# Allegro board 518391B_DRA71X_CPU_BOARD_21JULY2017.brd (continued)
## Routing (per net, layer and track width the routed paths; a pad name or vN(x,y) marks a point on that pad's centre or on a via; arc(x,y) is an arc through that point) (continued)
H_CSI2_DX1: length 83.1
  TOP w0.112: U27.AD1 100.85,91.95 101.61,91.95 102.39,92.73 102.39,93.49 103.14,94.23 108.58,94.23 108.74,94.08 109.45,94.08 115.7,100.33 133.99,100.33 136.8,97.51 151.24,97.51 151.74,98.02 156.36,98.02 157.2,97.18 157.2,95.4 157.48,95.12 157.48,93.63 157.67,93.45 158.86,93.45 159.06,93.65 159.06,95.95 159.38,96.27 159.89,96.27 160.21,95.95 160.21,94.7 160.43,94.49 163.01,94.49 163.37,94.13 163.37,91.97 163.79,91.55 164.05,91.55 164.16,91.66 164.16,91.96 164.27,92.07 164.49,92.07 164.6,91.96 164.6,91.66 164.72,91.55 164.95,91.55 165.16,91.76 v2(165.54,91.76)
  BOTTOM w0.112: v2(165.54,91.76) 165.41,91.62 P9.9
H_CSI2_DX2: length 82.3
  TOP w0.102: U27.AE2 100.11,92.62 100.12,92.62 100.12,92.8
  TOP w0.112: 100.12,92.8 100.12,93 102.24,95.12 108.46,95.12 114.81,101.47 134.49,101.47 137.03,98.93 151.14,98.93 151.24,99.03 160.68,99.03 163.82,95.89 163.82,95.64 164.08,95.38 v2(164.35,95.38)
  BOTTOM w0.112: v2(164.35,95.38) 164.08,95.38 163.82,95.64 163.82,96 163.96,96.14 164.6,96.14 166.07,94.66 166.07,93.05 165.85,92.82 165.72,92.82 165.61,92.71 165.61,92.51 165.75,92.38 165.94,92.38 166.07,92.25 166.07,90.12 165.93,89.98 165.29,89.98 165.14,90.13 P9.13
H_CSI2_DY0: length 82.6
  TOP w0.102: 101.15,90.88 100.44,90.88 U27.AB2
  TOP w0.112: 101.15,90.88 102.18,90.88 103.25,91.95 109.98,91.95 116.74,98.7 133.08,98.7 135.64,96.14 138.2,96.14 138.31,96.03 138.31,95.44 138.63,95.12 139.15,95.12 139.47,95.44 139.47,96.03 139.58,96.14 139.82,96.14 139.93,96.03 139.93,95.57 140.25,95.25 140.77,95.25 141.09,95.57 141.09,96.03 141.2,96.14 141.44,96.14 141.55,96.03 141.55,95.32 141.87,95 142.39,95 142.71,95.32 142.71,96.03 142.82,96.14 143.05,96.14 143.16,96.03 143.16,95.32 143.48,95 144,95 144.32,95.32 144.32,96.03 144.43,96.14 144.65,96.14 144.76,96.03 144.76,95.32 145.08,95 145.6,95 145.92,95.32 145.92,96.03 146.03,96.14 146.26,96.14 146.37,96.03 146.37,95.32 146.69,95 147.21,95 147.53,95.32 147.53,96.03 147.64,96.14 147.86,96.14 147.98,96.03 147.98,95.32 148.3,95 148.81,95 149.13,95.32 149.13,96.03 149.25,96.14 149.48,96.14 154.44,91.19 156.21,91.19 156.49,91.47 158.9,91.47 160.02,92.58 v2(162.31,92.58)
  BOTTOM w0.112: v2(162.31,92.58) 162.35,92.62 P9.7
H_CSI2_DY1: length 83.1
  TOP w0.102: 100.97,91.57 100.92,91.51 100.58,91.51 100.28,91.21 U27.AC2
  TOP w0.112: 100.97,91.57 100.98,91.57 101,91.59 101.76,91.59 102.75,92.58 102.75,92.8 102.75,93.34 103.29,93.88 108.43,93.88 108.59,93.72 109.6,93.72 115.85,99.97 133.84,99.97 136.66,97.16 151.38,97.16 151.89,97.66 156.21,97.66 156.84,97.03 156.84,95.26 157.12,94.98 157.12,93.49 157.52,93.09 159,93.09 159.41,93.5 159.41,95.8 159.52,95.91 159.75,95.91 159.86,95.8 159.86,94.55 160.28,94.13 162.86,94.13 163.02,93.98 163.02,91.82 163.64,91.2 164.96,91.2 165.16,91 v2(165.55,91)
  BOTTOM w0.112: v2(165.55,91) 165.42,91.13 P9.11
H_CSI2_DY2: length 82.3
  TOP w0.102: U27.AD2 100.12,92.02 100.44,92.34 100.44,92.76 100.47,92.8
  TOP w0.112: v2(163.46,95.38) 163.46,95.74 160.53,98.68 151.38,98.68 151.28,98.58 136.89,98.58 134.35,101.12 114.96,101.12 108.61,94.77 102.39,94.77 100.47,92.85 100.47,92.8
  BOTTOM w0.112: v2(163.46,95.38) 163.46,96.15 163.81,96.49 164.74,96.49 166.43,94.81 166.43,89.97 166.08,89.63 P9.15
H_DCAN1_RX: length 112
  TOP w0.127: v2(68.8,64.39) 68.8,64.43 68.71,64.52 68.71,69.05 68.25,69.5 v2(68.25,70.23) ; v1(86.14,81.13) U27.H23
  LY3 w0.133: v2(68.8,64.39) 70.36,62.83 70.36,53.21 75.06,48.51 75.06,47.37 76.58,45.85 76.58,42.54 80.77,38.35 106.68,38.35 110.87,34.16 123.82,34.16 124.84,35.18 127.25,35.18 129.03,36.96 v2(129.07,36.96)
  LY4 w0.133: v1(86.14,81.13) 84.13,79.12 83.95,79.12 82.17,77.34 81.28,77.34 80.39,76.45 79.38,76.45 77.22,74.3 76.34,74.3 74.94,72.9 71.62,72.9 69.34,70.62 69.34,70.61 68.96,70.23 v2(68.25,70.23)
  BOTTOM w0.127: R371.1 129.03,36.92 v2(129.07,36.96)
H_DCAN1_TX: length 120.9
  TOP w0.127: v1(86.79,81.13) U27.H22 ; v2(68.8,70.99) 68.8,69.32 69.01,69.1 69.01,64.85 69.22,64.65 69.22,64.15 v2(68.7,63.64)
  LY3 w0.133: v2(68.7,63.64) 69.85,62.48 69.85,53.21 74.68,48.39 74.68,47.24 76.2,45.72 76.2,42.42 86.74,31.88 92.84,31.88 94.23,33.27 107.66,33.27 108.55,32.38 119.51,32.38 120.02,32.89 127.51,32.89 130.05,35.43 130.05,37.08 129.54,37.59 128.14,37.59 v2(127.89,37.34)
  LY4 w0.133: v1(86.79,81.13) 86.39,81.53 85.85,81.53 81.92,77.6 80.16,77.6 77.11,74.56 76.23,74.56 74.83,73.16 71.51,73.16 69.35,70.99 v2(68.8,70.99)
  BOTTOM w0.127: R372.1 v2(127.89,37.34)
H_DDR1_A0: length 99.1
  TOP w0.102: U23.N3 v4(54.55,97) ; U29.N3 v4(54.55,82.77)
  TOP w0.127: R88.2 v2(53.85,72.58) ; U27.AC18 v1(90.04,91.53)
  LY3 w0.133: v2(53.85,72.58) 53.85,73.91 54.15,74.21 54.15,79.8 54.55,80.2 v4(54.55,82.77)
  LY4 w0.133: v1(90.04,91.53) 90.04,94.03 89.69,94.38 89.69,94.57 90.06,94.94 90.06,95.13 89.87,95.32 89.68,95.32 89.31,94.95 89.13,94.95 88.94,95.14 88.94,95.33 89.92,96.3 89.92,96.65 88.52,98.04 86.74,98.04 85.75,99.03 85.75,100.31 84.86,101.2 84.64,101.2 83.9,100.47 83.68,100.47 83.53,100.62 83.53,100.84 84.26,101.58 84.26,101.8 84.07,101.98 83.19,101.98 82.38,101.18 82.38,100.5 82.26,100.39 72.33,100.39 72.24,100.47 71.98,100.47 71.85,100.61 71.85,101.05 71.72,101.18 71.45,101.18 71.32,101.05 71.32,100.61 71.18,100.47 70.92,100.47 70.78,100.61 70.78,101.05 70.65,101.18 70.38,101.18 70.25,101.05 70.25,100.61 70.12,100.47 69.77,100.47 69.63,100.34 69.63,99.59 69.5,99.46 69.23,99.46 69.1,99.59 69.1,100.34 68.97,100.47 68.7,100.47 68.57,100.34 68.57,99.59 68.43,99.46 68.17,99.46 68.03,99.59 68.03,100.34 67.9,100.47 67.63,100.47 67.5,100.34 67.5,99.59 67.37,99.46 67.1,99.46 66.97,99.59 66.97,100.34 66.81,100.5 63.42,100.5 63.26,100.34 63.26,100.11 63.11,99.95 62.89,99.95 62.73,100.11 62.73,100.34 62.57,100.5 62.06,100.5 62,100.56 60.22,100.56 60.06,100.41 60.06,100.11 59.9,99.95 59.68,99.95 59.53,100.11 59.53,100.41 59.37,100.56 59.15,100.56 58.99,100.41 58.99,100.11 58.84,99.95 58.62,99.95 58.46,100.11 58.46,100.41 58.3,100.56 58.04,100.56 57.91,100.43 57.91,99.71 57.78,99.58 57.51,99.58 57.38,99.71 57.38,100.43 57.24,100.56 56.98,100.56 56.84,100.43 56.84,99.71 56.71,99.58 56.44,99.58 56.31,99.71 56.31,100.43 56.18,100.56 55.52,100.56 54.95,99.99 54.95,97.4 v4(54.55,97)
  BOTTOM w0.127: v4(54.55,82.77) 54.14,83.18 54.14,83.73 53.91,83.97 53.55,83.97 53.35,84.16 53.35,84.52 52.71,85.17 52.68,85.17 52.68,88.95 54.95,91.22 54.95,93.38 55.32,93.75 55.32,94.19 55.19,94.31 53.19,94.31 53.06,94.44 53.06,94.7 53.19,94.82 55.19,94.82 55.32,94.95 55.32,95.96 55.04,96.24 54.67,96.24 54.55,96.37 v4(54.55,97)
H_DDR1_A1: length 95.2
  TOP w0.102: U29.P7 v4(53.75,78.77)
  TOP w0.127: v2(85.45,103.9) 85.45,103.2 86.61,102.03 86.61,100.27 88.07,98.81 88.07,98.36 87.55,97.84 87.55,95.9 89.06,94.39 U27.AE19 ; v4(53.75,93) U23.P7
  LY3 w0.133: v2(53.21,73.02) 53.21,73.66 53.09,73.79 53.09,75.43 53.35,75.7 53.35,78.38 v4(53.75,78.77) 53.75,80.1 54.15,80.5 54.15,84.53 53.35,85.33 53.35,85.57 53.22,85.7 52.15,85.7 52.02,85.83 52.02,86.1 52.15,86.23 53.22,86.23 53.35,86.37 53.35,86.63 53.22,86.77 52.15,86.77 52.02,86.9 52.02,87.17 52.15,87.3 53.22,87.3 53.35,87.43 53.35,92.6 v4(53.75,93)
  LY4 w0.133: v2(85.45,103.9) 85.02,103.48 69.24,103.48 68.09,102.33 67.79,102.33 67.66,102.46 67.66,103.41 67.52,103.54 67.26,103.54 67.12,103.41 67.12,102.46 66.99,102.33 66.72,102.33 66.59,102.46 66.59,103.41 66.46,103.54 66.19,103.54 66.06,103.41 66.06,102.46 65.92,102.33 65.66,102.33 65.52,102.46 65.52,103.41 65.39,103.54 65.12,103.54 64.99,103.41 64.99,102.46 64.86,102.33 64.59,102.33 64.46,102.46 64.46,103.41 64.32,103.54 64.06,103.54 63.92,103.41 63.92,102.46 63.79,102.33 63.52,102.33 63.39,102.46 63.39,103.41 63.26,103.54 62.99,103.54 62.86,103.41 62.86,102.46 62.72,102.33 53.98,102.33 51.73,100.08 51.73,96.3 53.75,94.28 v4(53.75,93)
  BOTTOM w0.127: v2(53.21,73.02) R284.2
H_DDR1_A2: length 108.6
  TOP w0.102: 89.39,93.24 89.39,92.18 U27.AD19 ; U23.P3 v4(53.75,97) ; U29.P3 v4(53.75,82.77)
  TOP w0.127: 89.39,93.24 89.39,94.42 87.86,95.95 87.86,97.78 88.33,98.25 88.33,98.92 86.89,100.35 86.89,102.16 86.33,102.72 v2(86.33,103.66) ; R85.2 v2(50.42,72.58)
  LY3 w0.133: v2(50.42,72.58) 50.42,77.7 53.75,81.03 v4(53.75,82.77)
  BOTTOM w0.127: v4(53.75,82.77) 53.35,83.17 52.78,83.17 52.54,83.4 52.54,83.73 52.54,84.67 52.2,85.01 52.2,89.13 54.15,91.09 54.15,92.84 54.14,92.85 54.14,93.64 53.87,93.9 52.98,93.9 52.63,94.26 52.63,95.2 52.76,95.33 54.64,95.33 54.76,95.45 54.76,95.71 54.64,95.83 52.76,95.83 52.63,95.96 52.63,96.22 52.86,96.44 53.59,96.44 53.75,96.6 v4(53.75,97) 53.35,97.39 53.35,104.11 53.77,104.52 54.15,104.52 54.28,104.39 54.28,102.76 54.41,102.64 54.63,102.64 54.79,102.8 54.79,104.39 54.92,104.52 55.17,104.52 55.3,104.39 55.3,102.85 55.46,102.68 55.64,102.68 55.81,102.85 55.81,104.39 55.93,104.52 56.31,104.52 56.44,104.39 56.44,103.6 56.57,103.48 56.82,103.48 56.95,103.6 56.95,104.39 57.07,104.52 57.33,104.52 57.45,104.39 57.45,103.6 57.58,103.48 57.84,103.48 57.96,103.6 57.96,104.39 58.09,104.52 58.34,104.52 58.47,104.39 58.47,103.6 58.6,103.48 58.85,103.48 58.98,103.6 58.98,104.39 59.11,104.52 59.36,104.52 59.49,104.39 59.49,103.6 59.61,103.48 59.87,103.48 59.99,103.6 59.99,104.39 60.12,104.52 60.38,104.52 60.5,104.39 60.5,103.6 60.63,103.48 60.88,103.48 61.01,103.6 61.01,104.39 61.14,104.52 61.39,104.52 61.52,104.39 61.52,103.6 61.65,103.48 61.9,103.48 62.03,103.6 62.03,104.39 62.15,104.52 62.41,104.52 62.53,104.39 62.53,103.6 62.66,103.48 83.24,103.48 84.08,104.32 85.67,104.32 v2(86.33,103.66)
H_DDR1_A3: length 102.3
  TOP w0.102: U23.N2 v4(54.55,97.8) ; U29.N2 v4(54.55,83.57)
  TOP w0.127: v1(87.38,90.8) 88.82,90.8 U27.AB19 ; R90.2 v2(56.13,72.58)
  LY3 w0.133: v2(56.13,72.58) 56.13,75.44 54.95,76.63 54.95,83.17 54.55,83.57 v4(54.55,83.57) 54.95,83.97 54.95,87.8 54.15,88.6 54.15,93.39 54.91,94.16 57.28,94.16 57.58,94.46 57.58,95.28 57.12,95.73 55.83,95.73 54.95,96.61 54.95,97.39 v4(54.55,97.8) 54.95,98.19 54.95,101.4 55.14,101.59 55.14,102.6 55.63,103.09 72.02,103.09 72.78,103.85 77.55,103.85 77.68,103.71 77.68,103.22 77.82,103.09 78.08,103.09 78.22,103.22 78.22,103.71 78.35,103.85 78.62,103.85 78.75,103.71 78.75,103.22 78.88,103.09 79.15,103.09 79.28,103.22 79.28,103.71 79.42,103.85 79.68,103.85 79.82,103.71 79.82,103.22 79.95,103.09 80.22,103.09 80.35,103.22 80.35,103.71 80.48,103.85 80.75,103.85 80.88,103.71 80.88,103.22 81.02,103.09 81.28,103.09 81.42,103.22 81.42,103.71 81.55,103.85 81.82,103.85 81.95,103.71 81.95,103.22 82.08,103.09 82.61,103.09 84.58,101.11 86.81,101.11 87.19,100.74 90.45,100.74 91.44,99.75 91.44,96.49 90.84,95.88 89.5,95.88 88.94,95.33 88.94,92.59 88.81,92.46 88.53,92.46 88.39,92.59 88.39,95.37 88.26,95.5 87.99,95.5 87.86,95.37 87.86,92.35 88.52,91.69 88.52,91.44 87.88,90.8 v1(87.38,90.8)
H_DDR1_A4: length 94.7
  TOP w0.102: U29.P8 v4(53.75,77.97) ; U27.AD20 88.09,92.18 88.09,93.24
  TOP w0.127: 88.09,93.24 88.09,94.28 86.79,95.58 86.79,99.37 85.7,100.47 85.7,102.46 84.89,103.28 84.89,103.57 v2(84.56,103.9) ; v4(53.75,92.2) U23.P8
  LY4 w0.133: v2(84.56,103.9) 62.59,103.9 61.7,103 61.21,103 61.08,103.14 61.08,103.85 60.94,103.98 60.68,103.98 60.54,103.85 60.54,103.14 60.41,103 60.14,103 60.01,103.14 60.01,103.85 59.88,103.98 59.61,103.98 59.48,103.85 59.48,103.14 59.34,103 59.08,103 58.94,103.14 58.94,103.85 58.81,103.98 58.54,103.98 58.41,103.85 58.41,103.14 58.28,103 58.01,103 57.88,103.14 57.88,103.85 57.74,103.98 57.48,103.98 57.34,103.85 57.34,103.14 57.21,103 56.94,103 56.81,103.14 56.81,103.85 56.68,103.98 56.41,103.98 56.27,103.85 56.27,103.14 56.14,103 55.87,103 55.74,103.14 55.74,103.85 55.61,103.98 55.34,103.98 55.21,103.85 55.21,103.14 55.07,103 54.19,103 51.43,100.25 51.43,95.93 53.35,94.01 53.35,92.6 v4(53.75,92.2) 53.34,91.79 53.34,91.23 53.11,91 52.31,91 51.81,91 51.33,90.53 51.33,90.27 51.2,90.13 50.86,90.13 50.72,90 50.72,89.73 50.86,89.6 51.2,89.6 51.33,89.47 51.33,88.43 51.2,88.3 50.91,88.3 50.77,88.16 50.77,87.9 50.91,87.76 51.2,87.76 51.33,87.63 51.33,79.38 51.54,79.17 53.11,79.17 53.34,78.94 53.34,78.38 v4(53.75,77.97) 53.35,77.57 53.35,75.56 54.36,74.55 v2(54.36,73.02)
  BOTTOM w0.127: v2(54.36,73.02) R283.2
H_DDR1_A5: length 104.3
  TOP w0.102: U29.P2 v4(53.75,83.57) ; U23.P2 v4(53.75,97.8)
  TOP w0.127: v2(86.18,101.55) 86.18,100.34 87.05,99.48 87.05,95.69 88.41,94.32 U27.AE20
  LY3 w0.133: v2(86.18,101.55) 84.75,101.55 81.85,104.45 72,104.45 71.87,104.32 71.87,103.66 71.73,103.53 71.47,103.53 71.33,103.66 71.33,104.32 71.2,104.45 70.93,104.45 70.8,104.32 70.8,103.66 70.67,103.53 70.4,103.53 70.27,103.66 70.27,104.32 70.13,104.45 69.86,104.45 69.73,104.32 69.73,103.66 69.6,103.53 69.33,103.53 69.2,103.66 69.2,104.32 69.06,104.45 68.8,104.45 68.66,104.32 68.66,103.66 68.53,103.53 68.26,103.53 68.13,103.66 68.13,104.32 68,104.45 67.73,104.45 67.6,104.32 67.6,103.66 67.46,103.53 67.2,103.53 67.06,103.66 67.06,104.32 66.93,104.45 66.66,104.45 66.53,104.32 66.53,103.66 66.4,103.53 66.13,103.53 66,103.66 66,104.32 65.86,104.45 65.6,104.45 65.46,104.32 65.46,103.66 65.33,103.53 65.06,103.53 64.93,103.66 64.93,104.32 64.8,104.45 64.53,104.45 64.4,104.32 64.4,103.66 64.26,103.53 64,103.53 63.86,103.66 63.86,104.32 63.73,104.45 63.46,104.45 63.33,104.32 63.33,103.66 63.2,103.53 62.93,103.53 62.8,103.66 62.8,104.32 62.66,104.45 62.4,104.45 62.26,104.32 62.26,103.66 62.13,103.53 61.86,103.53 61.73,103.66 61.73,104.32 61.6,104.45 61.33,104.45 61.2,104.32 61.2,103.66 61.06,103.53 60.8,103.53 60.66,103.66 60.66,104.32 60.53,104.45 60.26,104.45 60.13,104.32 60.13,103.66 60,103.53 59.73,103.53 59.6,103.66 59.6,104.32 59.46,104.45 59.2,104.45 59.06,104.32 59.06,103.66 58.93,103.53 58.66,103.53 58.53,103.66 58.53,104.32 58.4,104.45 58.13,104.45 58,104.32 58,103.66 57.86,103.53 54.92,103.53 54.55,103.16 54.55,102.55 54.74,102.36 54.74,101.77 54.33,101.36 54.03,101.36 53.7,101.02 53.7,99.35 54.15,98.9 54.15,98.2 v4(53.75,97.8) 54.15,97.39 54.15,96.9 54.14,96.89 54.14,96.08 53.64,95.58 51.97,95.58 51.64,95.25 51.64,95.01 51.77,94.88 52.52,94.88 52.65,94.75 52.65,94.48 52.52,94.35 51.77,94.35 51.64,94.21 51.64,85.29 52.07,84.86 53.02,84.86 53.35,84.53 53.35,83.97 v4(53.75,83.57) 53.35,83.17 53.35,81.14 49.78,77.57 v2(49.78,73.02)
  BOTTOM w0.127: v2(49.78,73.02) R287.2
H_DDR1_A6: length 92.7
  TOP w0.102: U23.R8 v4(52.95,92.2) ; U29.R8 v4(52.95,77.97)
  TOP w0.127: v1(90.04,89.58) U27.AA18 ; R87.2 v2(52.7,72.58)
  LY4 w0.133: v2(52.7,72.58) 52.7,74.04 52.55,74.2 52.55,77.57 v4(52.95,77.97) 52.54,78.38 52.31,78.38 51.62,78.38 50.04,79.96 50.04,80.22 50.17,80.35 50.74,80.35 50.88,80.49 50.88,80.75 50.74,80.89 50.17,80.89 50.04,81.02 50.04,90.91 50.92,91.79 52.54,91.79 v4(52.95,92.2) 52.55,92.59 52.55,94.13 51.13,95.55 51.13,100.41 55.05,104.32 87.26,104.32 92.2,99.38 92.2,92.46 92.36,92.3 92.36,90.71 91.24,89.58 v1(90.04,89.58)
H_DDR1_A7: length 103.2
  TOP w0.102: U29.R2 v4(52.95,83.57) ; U23.R2 v4(52.95,97.8)
  TOP w0.127: U27.AA20 v1(88.09,90.23)
  LY3 w0.133: v1(88.09,90.23) 88.09,90.5 88.9,91.31 88.9,91.95 89.48,92.53 89.48,95.12 89.62,95.25 89.97,95.25 90.1,95.12 90.1,92.48 90.23,92.35 90.52,92.35 90.64,92.47 90.64,95.05 91.8,96.22 91.8,99.86 90.61,101.06 87.49,101.06 86.55,101.99 85.68,101.99 85.55,101.86 84.86,101.86 81.99,104.73 57.43,104.73 57.3,104.6 57.3,104.05 57.17,103.92 56.9,103.92 56.77,104.05 56.77,104.6 56.63,104.73 56.37,104.73 56.23,104.6 56.23,104.05 56.1,103.92 55.83,103.92 55.7,104.05 55.7,104.6 55.57,104.73 55.3,104.73 55.17,104.6 55.17,104.05 55.03,103.92 54.77,103.92 54.63,104.05 54.63,104.6 54.5,104.73 54.14,104.73 53.35,103.94 53.35,98.2 v4(52.95,97.8) 53.34,97.4 53.34,96.55 52.86,96.06 51.49,96.06 51.16,95.73 51.16,86.35 51.02,86.22 50.63,86.22 50.5,86.09 50.5,85.82 50.63,85.69 51.02,85.69 51.16,85.55 51.16,85.29 51.02,85.15 50.63,85.15 50.5,85.02 50.5,84.75 50.63,84.62 51.02,84.62 51.16,84.49 51.16,84.25 51.44,83.97 52.31,83.97 52.71,83.57 v4(52.95,83.57) 52.55,83.17 52.55,82.04 48.64,78.13 v2(48.64,73.02)
  BOTTOM w0.127: v2(48.64,73.02) R288.2
H_DDR1_A8: length 99.3
  TOP w0.102: U23.T8 v4(52.15,92.2) ; U29.T8 v4(52.15,77.97)
  TOP w0.127: U27.Y21 v1(87.44,89.58) ; R86.2 v2(51.56,72.58)
  LY4 w0.133: v4(52.15,92.2) 50.54,92.2 49.53,91.19 49.53,79.62 49.66,79.49 49.9,79.49 50.04,79.36 50.04,79.09 49.9,78.96 49.66,78.96 49.53,78.82 49.53,78.11 49.66,77.97 v4(52.15,77.97) 51.41,77.24 51.41,73.68 51.56,73.53 v2(51.56,72.58) ; v2(88.39,96.39) 87.88,95.88 87.88,94.36 88.65,93.6 88.65,91.44 87.44,90.23 v1(87.44,89.58)
  BOTTOM w0.127: v2(88.39,96.39) 89.53,97.54 89.53,103.38 87.84,105.08 75.61,105.08 75.44,104.9 74.09,104.9 73.91,105.08 72.69,105.08 72.57,104.95 72.57,104.48 72.44,104.35 72.19,104.35 72.06,104.48 72.06,104.95 71.93,105.08 71.68,105.08 71.55,104.95 71.55,104.48 71.42,104.35 71.17,104.35 71.04,104.48 71.04,104.95 70.92,105.08 70.66,105.08 70.53,104.95 70.53,104.48 70.41,104.35 70.15,104.35 70.03,104.48 70.03,104.95 69.9,105.08 69.65,105.08 69.52,104.95 69.52,104.48 69.39,104.35 69.14,104.35 69.01,104.48 69.01,104.95 68.88,105.08 52.24,105.08 51.74,104.58 51.74,94.03 52.54,93.23 52.54,92.83 52.15,92.44 v4(52.15,92.2)
H_DDR1_A9: length 108.6
  TOP w0.102: U23.R3 v4(52.95,97) ; U29.R3 v4(52.95,82.77)
  TOP w0.127: R84.2 v2(49.28,72.58) ; U27.AC20 v1(88.09,91.53)
  LY3 w0.133: v2(49.28,72.58) 49.28,77.46 52.95,81.13 v4(52.95,82.77)
  BOTTOM w0.127: v4(52.95,82.77) 52.95,82.09 52.82,81.96 52.48,81.96 52.35,81.84 52.35,81.58 52.48,81.45 52.82,81.45 52.95,81.33 52.95,80.79 52.73,80.56 52.07,80.56 51.75,80.89 51.75,84.21 51.75,89.52 53.34,91.11 53.34,93.16 52.93,93.57 52.73,93.57 52.17,94.13 52.17,96.22 v4(52.95,97) 52.55,97.39 52.55,104.49 52.86,104.8 63.14,104.8 63.26,104.67 63.26,104.03 63.39,103.9 63.64,103.9 63.77,104.03 63.77,104.67 63.9,104.8 64.15,104.8 64.28,104.67 64.28,104.03 64.41,103.9 64.66,103.9 64.79,104.03 64.79,104.67 64.91,104.8 65.17,104.8 65.3,104.67 65.3,104.03 65.42,103.9 65.68,103.9 65.8,104.03 65.8,104.67 65.93,104.8 66.18,104.8 66.31,104.67 66.31,104.03 66.44,103.9 82.82,103.9 83.57,104.65 87.63,104.65 89.15,103.12 89.15,101.35 88.01,100.2 88.01,97.84 86.85,96.68 86.85,92.71 86.72,92.59 86.34,92.59 86.24,92.69 86.24,95.5 86.01,95.73 85.69,95.73 85.54,95.58 85.54,92.21 85.67,92.08 87.54,92.08 v1(88.09,91.53)
H_DDR1_A10: length 96.9
  TOP w0.102: U23.L7 v4(56.15,93) ; U29.L7 v4(56.15,78.77)
  TOP w0.127: v2(86.26,96.72) 86.26,98.4 86.03,98.63 85.01,98.63 84.89,98.5 84.89,98.22 84.76,98.09 84.51,98.09 84.38,98.22 84.38,98.5 84.25,98.63 83.94,98.63 83.81,98.5 83.81,97.05 83.68,96.92 83.43,96.92 83.3,97.05 83.3,98.5 83.18,98.63 82.92,98.63 82.79,98.76 82.79,99.31 82.67,99.44 82.41,99.44 82.29,99.31 82.29,98.76 82.16,98.63 81.91,98.63 81.78,98.76 81.78,99.31 81.65,99.44 81.4,99.44 81.27,99.31 81.27,98.76 81.14,98.63 80.89,98.63 80.76,98.76 80.76,99.31 80.64,99.44 80.38,99.44 80.25,99.31 80.25,98.76 80.13,98.63 79.87,98.63 79.75,98.76 79.75,99.31 79.62,99.44 79.37,99.44 79.24,99.31 79.24,98.76 79.11,98.63 78.86,98.63 78.73,98.76 78.73,99.31 78.6,99.44 78.35,99.44 78.22,99.31 78.22,98.76 78.1,98.63 77.84,98.63 77.71,98.76 77.71,99.31 77.59,99.44 77.33,99.44 77.21,99.31 77.21,98.76 77.08,98.63 76.83,98.63 76.7,98.76 76.7,99.31 76.57,99.44 76.32,99.44 76.19,99.31 76.19,98.76 76.06,98.63 75.81,98.63 75.68,98.76 75.68,99.31 75.56,99.44 75.3,99.44 75.17,99.31 75.17,98.76 75.05,98.63 74.79,98.63 74.67,98.76 74.67,99.31 74.54,99.44 74.29,99.44 74.16,99.31 74.16,98.76 74.03,98.63 73.78,98.63 73.65,98.76 73.65,99.31 73.52,99.44 73.27,99.44 73.14,99.31 73.14,98.76 73.02,98.63 72.76,98.63 72.63,98.76 72.63,99.31 72.51,99.44 72.25,99.44 72.13,99.31 72.13,98.76 72,98.63 71.75,98.63 71.62,98.76 71.62,99.31 71.49,99.44 71.24,99.44 71.11,99.31 71.11,98.76 70.98,98.63 70.73,98.63 70.6,98.76 70.6,99.31 70.48,99.44 70.22,99.44 70.09,99.31 70.09,98.76 69.97,98.63 69.71,98.63 69.59,98.76 69.59,99.31 69.46,99.44 69.21,99.44 69.08,99.31 69.08,98.76 68.95,98.63 68.7,98.63 68.57,98.76 68.57,99.31 68.44,99.44 68.19,99.44 68.06,99.31 68.06,97.32 67.93,97.19 67.75,97.19 67.62,97.32 67.62,98.26 67.62,98.26 67.62,99.16 67.5,99.28 67.25,99.28 67.13,99.15 67.13,97.18 66.53,96.58 66.53,95.33 66.07,94.87 56.68,94.87 56.55,94.74 U23.L7 ; R92.2 v2(58.42,72.58) ; v1(87,90.3) 87.38,90.3 U27.AA21
  LY4 w0.133: v1(87,90.3) 86.56,89.86 85.91,89.86 85.34,90.42 85.34,95.81 v2(86.26,96.72) ; v4(56.15,93) 56.55,91.54 56.55,79.17 v4(56.15,78.77) 56.55,78.37 56.55,75.91 58.17,74.3 58.17,73.41 58.42,73.15 v2(58.42,72.58)
H_DDR1_A11: length 100.9
  TOP w0.102: U23.R7 v4(52.95,93) ; U29.R7 v4(52.95,78.77)
  TOP w0.127: U23.R7 53.35,94.65 54.33,95.63 64.5,95.63 66.06,97.2 66.06,101.99 66.63,102.56 67.19,102.56 67.32,102.69 67.32,103.36 67.44,103.48 67.7,103.48 67.82,103.36 67.82,102.69 67.95,102.56 68.2,102.56 68.33,102.69 68.33,103.36 68.46,103.48 68.71,103.48 68.84,103.36 68.84,102.69 68.97,102.56 69.22,102.56 69.35,102.69 69.35,103.36 69.47,103.48 69.73,103.48 69.86,103.36 69.86,102.69 69.98,102.56 70.24,102.56 70.36,102.69 70.36,103.36 70.49,103.48 70.74,103.48 70.87,103.36 70.87,102.69 71,102.56 71.25,102.56 71.38,102.69 71.38,103.36 71.51,103.48 71.76,103.48 71.89,103.36 71.89,102.69 72.01,102.56 72.27,102.56 72.4,102.69 72.4,103.36 72.52,103.48 72.78,103.48 72.9,103.36 72.9,102.69 73.03,102.56 73.28,102.56 73.41,102.69 73.41,103.36 73.54,103.48 73.79,103.48 73.92,103.36 73.92,102.69 74.05,102.56 74.3,102.56 74.43,102.69 74.43,103.36 74.55,103.48 74.81,103.48 74.94,103.36 74.94,102.69 75.06,102.56 75.32,102.56 75.44,102.69 75.44,103.36 75.57,103.48 75.82,103.48 75.95,103.36 75.95,102.69 76.08,102.56 76.33,102.56 76.46,102.69 76.46,103.36 76.59,103.48 76.84,103.48 76.97,103.36 76.97,102.69 77.09,102.56 77.35,102.56 77.48,102.69 77.48,103.36 77.6,103.48 77.86,103.48 77.98,103.36 77.98,102.69 78.11,102.56 78.36,102.56 78.49,102.69 78.49,103.36 78.62,103.48 78.87,103.48 79,103.36 79,102.69 79.13,102.56 79.38,102.56 79.51,102.69 79.51,103.36 79.63,103.48 79.89,103.48 80.02,103.36 80.02,102.69 80.14,102.56 80.4,102.56 80.52,102.69 80.52,103.36 80.65,103.48 80.9,103.48 81.03,103.36 81.03,102.69 81.16,102.56 81.41,102.56 81.54,102.69 81.54,103.36 81.67,103.48 81.92,103.48 82.05,103.36 82.05,102.69 82.17,102.56 82.43,102.56 82.56,102.69 82.56,103.36 82.68,103.48 82.94,103.48 83.06,103.36 83.06,102.69 83.19,102.56 83.88,102.56 84.58,101.85 84.58,100.36 v2(84.07,99.85) ; U27.AC21 v1(87.44,91.53)
  LY3 w0.133: v2(52.07,73.02) 52.07,73.53 52.54,74.01 52.54,78.37 v4(52.95,78.77) ; v1(87.44,91.53) 87.44,96.91 85.24,99.11 85.24,99.77 84.99,100.03 84.25,100.03 v2(84.07,99.85)
  BOTTOM w0.127: v4(52.95,78.77) 51.66,80.06 51.66,80.39 51.36,80.7 51.36,89.99 52.54,91.17 52.54,92.3 52.55,92.32 52.55,92.36 52.95,92.75 v4(52.95,93) ; v2(52.07,73.02) R285.2
H_DDR1_A12: length 100.4
  TOP w0.102: U29.N7 v4(54.55,78.77)
  TOP w0.127: v4(54.55,93) U23.N7 54.95,94.67 55.65,95.38 64.6,95.38 66.46,97.23 66.46,101.1 66.6,101.24 67.2,101.24 67.33,101.37 67.33,102.18 67.45,102.3 67.71,102.3 67.84,102.18 67.84,101.37 67.96,101.24 68.22,101.24 68.34,101.37 68.34,102.18 68.47,102.3 68.72,102.3 68.85,102.18 68.85,101.37 68.98,101.24 69.23,101.24 69.36,101.37 69.36,102.18 69.49,102.3 69.74,102.3 69.87,102.18 69.87,101.37 69.99,101.24 70.25,101.24 70.38,101.37 70.38,102.18 70.5,102.3 70.76,102.3 70.88,102.18 70.88,101.37 71.01,101.24 71.26,101.24 71.39,101.37 71.39,102.18 71.52,102.3 71.77,102.3 71.9,102.18 71.9,101.37 72.03,101.24 72.28,101.24 72.41,101.37 72.41,102.18 72.53,102.3 72.79,102.3 72.92,102.18 72.92,101.37 73.04,101.24 73.3,101.24 73.42,101.37 73.42,102.18 73.55,102.3 73.8,102.3 73.93,102.18 73.93,101.37 74.06,101.24 74.31,101.24 74.44,101.37 74.44,102.18 74.57,102.3 74.82,102.3 74.95,102.18 74.95,101.37 75.07,101.24 75.33,101.24 75.46,101.37 75.46,102.18 75.58,102.3 75.84,102.3 75.96,102.18 75.96,101.37 76.09,101.24 76.34,101.24 76.47,101.37 76.47,102.18 76.6,102.3 76.85,102.3 76.98,102.18 76.98,101.37 77.11,101.24 77.36,101.24 77.49,101.37 77.49,102.18 77.61,102.3 77.87,102.3 78,102.18 78,101.37 78.12,101.24 78.38,101.24 78.5,101.37 78.5,102.18 78.63,102.3 78.88,102.3 79.01,102.18 79.01,101.37 79.14,101.24 79.39,101.24 79.52,101.37 79.52,102.18 79.65,102.3 79.9,102.3 80.03,102.18 80.03,101.37 80.15,101.24 80.41,101.24 80.54,101.37 80.54,102.18 80.66,102.3 80.92,102.3 81.04,102.18 81.04,101.37 81.17,101.24 81.42,101.24 81.55,101.37 81.55,102.18 81.68,102.3 81.93,102.3 82.06,102.18 82.06,101.37 82.19,101.24 82.44,101.24 82.57,101.37 82.57,102.18 82.69,102.3 82.95,102.3 83.08,102.18 83.08,101.37 83.2,101.24 83.93,101.24 84.17,100.99 84.17,100.68 83.65,100.16 83.65,99.67 83.98,99.35 84.54,99.35 v2(84.73,99.54) ; U27.AC22 v1(86.79,91.53)
  LY3 w0.133: v2(84.73,99.54) 84.73,99.03 86.79,96.98 v1(86.79,91.53)
  LY4 w0.133: v2(55.5,73.02) 55.5,74.42 54.61,75.31 54.61,76.07 54.95,76.41 54.95,78.37 v4(54.55,78.77) 54.95,79.17 54.95,85.39 54.67,89.23 54.67,90.14 54.95,91.16 54.95,92.38 v4(54.55,93)
  BOTTOM w0.127: v2(55.5,73.02) R282.2
H_DDR1_A13: length 99
  TOP w0.102: U23.T3 v4(52.15,97) ; U29.T3 v4(52.15,82.77)
  TOP w0.127: R83.2 v2(48.13,72.58) ; U27.AC15 v1(91.99,91.53)
  LY3 w0.133: v2(48.13,72.58) 48.13,78.31 52.15,82.32 v4(52.15,82.77) 49.92,82.77 49.43,83.26 49.43,96.65 50.19,97.41 51.73,97.41 v4(52.15,97)
  LY4 w0.133: v4(52.15,97) 52.55,97.4 52.55,100.45 53.53,101.43 67.83,101.43 69.57,103.17 69.93,103.17 70.06,103.04 70.06,102.18 70.19,102.04 70.46,102.04 70.59,102.18 70.59,103.04 70.73,103.17 70.99,103.17 71.13,103.04 71.13,102.18 71.26,102.04 71.53,102.04 71.66,102.18 71.66,103.04 71.79,103.17 72.06,103.17 72.19,103.04 72.19,102.18 72.33,102.04 72.59,102.04 72.73,102.18 72.73,103.04 72.86,103.17 73.13,103.17 73.26,103.04 73.26,102.18 73.39,102.04 73.66,102.04 73.79,102.18 73.79,103.04 73.93,103.17 74.19,103.17 74.33,103.04 74.33,102.18 74.46,102.04 74.73,102.04 74.86,102.18 74.86,103.04 74.99,103.17 75.26,103.17 75.39,103.04 75.39,102.27 75.53,102.14 75.94,102.14 76.07,102.27 76.07,102.62 76.63,103.17 86.06,103.17 87.37,101.86 88.03,101.86 88.15,101.98 89,101.98 91.82,99.17 91.82,95.12 91.2,94.5 91.2,92.69 91.99,91.91 v1(91.99,91.53)
H_DDR1_A14: length 100.1
  TOP w0.102: U23.T7 v4(52.15,93) ; U29.T7 v4(52.15,78.77)
  TOP w0.127: v1(91.99,90.88) U27.AB15 ; U23.T7 52.55,95.47 52.96,95.88 64.39,95.88 65.64,97.13 65.64,103.36 66.05,103.77 66.78,103.77 66.91,103.9 66.91,104.39 67.04,104.52 67.29,104.52 67.42,104.39 67.42,103.9 67.54,103.77 67.8,103.77 67.93,103.9 67.93,104.39 68.05,104.52 68.31,104.52 68.43,104.39 68.43,103.9 68.56,103.77 68.81,103.77 68.94,103.9 68.94,104.39 69.07,104.52 69.32,104.52 69.45,104.39 69.45,103.9 69.58,103.77 69.83,103.77 69.96,103.9 69.96,104.39 70.08,104.52 70.34,104.52 70.47,104.39 70.47,103.9 70.59,103.77 70.85,103.77 70.97,103.9 70.97,104.39 71.1,104.52 71.35,104.52 71.48,104.39 71.48,103.9 71.61,103.77 71.86,103.77 71.99,103.9 71.99,104.39 72.12,104.52 72.37,104.52 72.5,104.39 72.5,103.9 72.62,103.77 72.88,103.77 73.01,103.9 73.01,104.39 73.13,104.52 73.39,104.52 73.51,104.39 73.51,103.9 73.64,103.77 73.89,103.77 74.02,103.9 74.02,104.39 74.15,104.52 74.4,104.52 74.53,104.39 74.53,103.9 74.66,103.77 74.91,103.77 75.04,103.9 75.04,104.39 75.16,104.52 75.42,104.52 75.55,104.39 75.55,103.9 75.67,103.77 75.93,103.77 76.05,103.9 76.05,104.39 76.18,104.52 76.43,104.52 76.56,104.39 76.56,103.9 76.69,103.77 76.94,103.77 77.07,103.9 77.07,104.39 77.2,104.52 77.45,104.52 77.58,104.39 77.58,103.9 77.7,103.77 77.96,103.77 78.09,103.9 78.09,104.39 78.21,104.52 78.47,104.52 78.59,104.39 78.59,103.9 78.72,103.77 78.97,103.77 79.1,103.9 79.1,104.39 79.23,104.52 79.48,104.52 79.61,104.39 79.61,103.9 79.74,103.77 83.63,103.77 v2(85.09,102.31)
  LY3 w0.133: v2(50.93,73.02) 50.93,77.55 v4(52.15,78.77) ; v2(85.09,102.31) 86.67,102.31 87.19,101.8 87.97,101.8 88.12,101.95 90.2,101.95 92.43,99.72 92.43,91.33 v1(91.99,90.88)
  BOTTOM w0.127: v2(50.93,73.02) R286.2 ; v4(52.15,78.77) 51.28,79.64 51.28,80.09 50.25,81.42 50.25,90.58 v4(52.15,93)
H_DDR1_A15: length 96.3
  TOP w0.102: U29.M7 v4(55.35,78.77) ; U23.M7 v4(55.35,93)
  TOP w0.127: v2(86.23,99.34) 85.38,99.34 85.1,99.06 83.69,99.06 83.16,99.59 83.16,99.95 83.04,100.08 82.63,100.08 82.51,99.95 82.51,99.82 82.38,99.69 82.13,99.69 82,99.82 82,100.54 81.87,100.67 81.62,100.67 81.49,100.54 81.49,99.82 81.36,99.69 81.11,99.69 80.98,99.82 80.98,100.54 80.86,100.67 80.6,100.67 80.47,100.54 80.47,99.82 80.35,99.69 80.09,99.69 79.97,99.82 79.97,100.54 79.84,100.67 79.59,100.67 79.46,100.54 79.46,99.82 79.33,99.69 79.08,99.69 78.95,99.82 78.95,100.54 78.82,100.67 78.57,100.67 78.44,100.54 78.44,99.82 78.32,99.69 78.06,99.69 77.93,99.82 77.93,100.54 77.81,100.67 77.55,100.67 77.43,100.54 77.43,99.82 77.3,99.69 77.05,99.69 76.92,99.82 76.92,100.54 76.79,100.67 76.54,100.67 76.41,100.54 76.41,99.82 76.28,99.69 76.03,99.69 75.9,99.82 75.9,100.54 75.78,100.67 75.52,100.67 75.39,100.54 75.39,99.82 75.27,99.69 75.01,99.69 74.89,99.82 74.89,100.54 74.76,100.67 74.51,100.67 74.38,100.54 74.38,99.82 74.25,99.69 74,99.69 73.87,99.82 73.87,100.54 73.74,100.67 73.49,100.67 73.36,100.54 73.36,99.82 73.24,99.69 72.98,99.69 72.85,99.82 72.85,100.54 72.73,100.67 72.47,100.67 72.35,100.54 72.35,99.82 72.22,99.69 71.97,99.69 71.84,99.82 71.84,100.54 71.71,100.67 71.46,100.67 71.33,100.54 71.33,99.82 71.2,99.69 70.95,99.69 70.82,99.82 70.82,100.54 70.7,100.67 70.44,100.67 70.31,100.54 70.31,99.82 70.19,99.69 69.93,99.69 69.81,99.82 69.81,100.54 69.68,100.67 69.43,100.67 69.3,100.54 69.3,99.82 69.17,99.69 68.92,99.69 68.79,99.82 68.79,100.54 68.66,100.67 68.41,100.67 68.28,100.54 68.28,99.82 68.16,99.69 67.9,99.69 67.77,99.82 67.77,100.54 67.65,100.67 67.39,100.67 67.27,100.54 67.27,100.18 66.8,99.71 66.8,97.21 64.71,95.12 55.88,95.12 55.46,94.71 55.46,94.53 55.59,94.4 56.05,94.4 56.22,94.23 56.22,93.83 55.79,93.4 U23.M7 ; U27.AC16 v1(90.69,91.53)
  LY4 w0.133: v2(56.64,73.02) 56.64,74.3 55.75,75.19 55.75,78.37 v4(55.35,78.77) 55.75,80 55.75,84.61 55.31,85.83 55.31,88.06 55.75,90.84 55.75,92.37 v4(55.35,93) ; v1(90.69,91.53) 90.32,91.9 90.32,96.88 87.86,99.34 v2(86.23,99.34)
  BOTTOM w0.127: v2(56.64,73.02) R281.2
H_DDR1_BA0: length 103.6
  TOP w0.102: U23.M2 v4(55.35,97.8) ; U29.M2 v4(55.35,83.57)
  TOP w0.127: U27.AE16 91.01,93.24 90.89,93.36 90.89,94.8 90.89,95.06 90.09,95.86 90.09,97.33 90.58,97.82 90.58,99.36 89.84,100.1 v2(88.98,100.1)
  LY3 w0.133: v2(57.78,73.02) 57.78,75.56 55.75,77.6 55.75,83.17 v4(55.35,83.57) 56.21,84.43 56.21,86.58 55.33,87.45 55.33,88.66 55.54,88.87 55.54,90.43 54.94,91.03 54.94,93.27 55.45,93.78 57.58,93.78 58.04,94.23 58.04,95.71 57.63,96.11 56.47,96.11 55.75,96.83 55.75,97.39 v4(55.35,97.8) 55.83,98.28 55.83,98.86 55.27,99.42 55.27,100.63 56.21,101.57 56.21,102.27 56.72,102.78 56.99,102.78 57.12,102.65 57.12,101.63 57.25,101.5 57.52,101.5 57.65,101.63 57.65,102.65 57.79,102.78 58.05,102.78 58.19,102.65 58.19,101.63 58.32,101.5 58.59,101.5 58.72,101.63 58.72,102.65 58.85,102.78 59.12,102.78 59.25,102.65 59.25,101.63 59.39,101.5 59.65,101.5 59.79,101.63 59.79,102.65 59.92,102.78 72.24,102.78 73.01,103.55 76.87,103.55 77.69,102.73 82.39,102.73 84.27,100.85 86.51,100.85 87.02,100.33 88.24,100.33 88.52,100.05 88.52,99.7 88.65,99.57 90.22,99.57 90.7,99.09 90.7,97.66 90.47,97.43 89.36,97.43 89.03,97.11 89.03,96.32 89.17,96.19 89.89,96.19 90.07,96.37 90.07,96.55 90.39,96.87 90.77,96.87 91.18,97.28 91.18,99.55 90.63,100.1 v2(88.98,100.1)
  BOTTOM w0.127: v2(57.78,73.02) R280.2
H_DDR1_BA1: length 93.1
  TOP w0.102: U29.N8 v4(54.55,77.97)
  TOP w0.127: v4(54.55,92.2) U23.N8 ; v1(90.69,90.23) U27.AA16 ; R89.2 v2(54.99,72.58)
  LY4 w0.133: v1(90.69,90.23) 91.44,90.99 91.44,91.83 90.93,92.34 90.93,95.21 91.44,95.72 91.44,99.07 89.48,101.03 87.18,101.03 86.74,101.47 86.74,101.73 85.61,102.85 82.05,102.85 81.92,102.72 81.92,102.1 81.79,101.97 81.52,101.97 81.39,102.1 81.39,102.72 81.25,102.85 80.99,102.85 80.85,102.72 80.85,102.1 80.72,101.97 80.45,101.97 80.32,102.1 80.32,102.72 80.19,102.85 79.92,102.85 79.79,102.72 79.79,102.1 79.65,101.97 79.39,101.97 79.25,102.1 79.25,102.72 79.12,102.85 78.85,102.85 78.72,102.72 78.72,102.1 78.59,101.97 78.32,101.97 78.19,102.1 78.19,102.72 78.05,102.85 77.33,102.85 76.83,102.36 76.83,102.12 76.5,101.78 70.08,101.78 70.08,101.79 68.88,101.79 68.18,101.08 53.86,101.08 53.34,100.56 53.34,96.11 54.15,95.3 54.15,92.59 v4(54.55,92.2) 54.14,91.79 54.14,91.13 53.59,90.58 52.3,90.58 51.74,90.02 51.74,89.76 51.87,89.62 52.42,89.62 52.55,89.49 52.55,89.22 52.42,89.09 51.87,89.09 51.74,88.96 51.74,79.96 52.07,79.63 53.75,79.63 54.15,79.23 54.15,78.37 v4(54.55,77.97) 54.15,77.57 54.15,75.27 54.99,74.42 v2(54.99,72.58)
H_DDR1_BA2: length 101.8
  TOP w0.102: U29.M3 v4(55.35,82.77) ; U23.M3 v4(55.35,97)
  TOP w0.127: U27.AB16 v1(90.69,90.88) ; R91.2 v2(57.28,72.58)
  LY4 w0.133: v4(55.35,97) 55.35,96.38 54.9,95.94 54.38,95.94 54.15,96.17 54.15,98.91 54.65,99.41 54.65,100.5 54.98,100.82 68.52,100.82 69.14,101.45 72.33,101.45 72.47,101.31 72.47,100.8 72.6,100.67 72.87,100.67 73,100.8 73,101.31 73.13,101.45 73.4,101.45 73.53,101.31 73.53,100.8 73.67,100.67 73.93,100.67 74.07,100.8 74.07,101.31 74.2,101.45 74.47,101.45 74.6,101.31 74.6,100.8 74.73,100.67 75,100.67 75.13,100.8 75.13,101.31 75.27,101.45 75.53,101.45 75.67,101.31 75.67,100.8 75.8,100.67 76.07,100.67 76.2,100.8 76.2,101.31 76.33,101.45 76.6,101.45 76.73,101.31 76.73,100.8 76.87,100.67 77.13,100.67 77.27,100.8 77.27,101.31 77.4,101.45 77.67,101.45 77.8,101.31 77.8,100.8 77.93,100.67 78.2,100.67 78.33,100.8 78.33,101.31 78.47,101.45 78.73,101.45 78.87,101.31 78.87,100.8 79,100.67 79.27,100.67 79.4,100.8 79.4,101.31 79.53,101.45 79.8,101.45 79.93,101.31 79.93,100.8 80.07,100.67 80.33,100.67 80.47,100.8 80.47,101.31 80.6,101.45 80.87,101.45 81,101.31 81,100.8 81.13,100.67 81.4,100.67 81.53,100.8 81.53,101.31 81.67,101.45 82.12,101.45 83.19,102.51 84.16,102.51 86.03,100.64 89.35,100.64 91.06,98.93 91.06,95.86 90.63,95.43 90.63,92.13 91.07,91.69 91.07,91.27 v1(90.69,90.88)
  BOTTOM w0.127: v4(55.35,97) 55.35,96.54 55.74,96.15 55.74,91.23 55.51,91 55.34,91 54.36,90.02 54.36,89.84 54.74,89.46 54.74,89.28 54.56,89.1 54.38,89.1 54,89.48 53.82,89.48 53.11,88.77 53.11,88.52 53.24,88.39 53.64,88.39 53.77,88.27 53.77,88.01 53.64,87.88 53.24,87.88 53.11,87.76 53.11,87.28 53.24,87.16 53.72,87.16 53.85,87.03 53.85,86.77 53.72,86.65 53.24,86.65 53.11,86.52 53.11,86.27 53.24,86.14 53.54,86.14 53.67,86.01 53.67,85.76 53.54,85.63 53.24,85.63 53.11,85.5 53.11,85.25 53.6,84.77 53.91,84.77 54.14,84.54 54.14,84.22 54.4,83.97 54.71,83.97 54.94,83.73 54.94,83.42 54.97,83.4 54.97,83.15 v4(55.35,82.77) 55.35,81.69 53.35,79.69 53.35,76.62 55.22,74.75 55.91,74.75 57.28,73.38 v2(57.28,72.58)
H_DDR1_CASN: length 110.2
  TOP w0.102: U29.K3 v4(56.95,82.77) ; 91.27,93.24 91.27,92.75 91.34,92.69 91.34,92.18 U27.AD16 ; U23.K3 v4(56.95,97)
  TOP w0.127: v2(88.02,102.96) 88.3,102.96 90.93,100.33 90.93,96.38 91.15,96.17 91.15,93.51 91.27,93.39 91.27,93.24 ; v2(61.85,72.58) R95.2
  LY4 w0.133: v4(56.95,82.77) 56.95,79.53 57.35,79.13 57.35,76.26 58.97,74.63 60.62,74.63 61.85,73.4 v2(61.85,72.58)
  BOTTOM w0.127: v4(56.95,82.77) 57.35,83.18 57.35,83.73 58.52,84.9 58.52,86.06 57.2,87.38 57.2,88.75 57.78,89.33 57.78,91.6 57.58,91.8 57.35,92.03 57.35,93.27 58.45,94.36 60.86,94.36 61.16,94.67 61.16,95.22 60.81,95.58 58.36,95.58 v4(56.95,97) 57.34,97.39 57.34,99.27 57.72,99.65 59.59,99.65 59.8,99.86 59.8,102.66 59.93,102.79 66.57,102.79 66.74,102.63 66.74,101.71 66.86,101.58 67.12,101.58 67.24,101.71 67.24,102.63 67.37,102.76 67.62,102.76 67.75,102.63 67.75,101.71 67.88,101.58 68.13,101.58 68.26,101.71 68.26,102.63 68.39,102.76 68.64,102.76 68.77,102.63 68.77,101.71 68.89,101.58 69.15,101.58 69.28,101.71 69.28,102.63 69.4,102.76 69.66,102.76 69.78,102.63 69.78,101.71 69.91,101.58 70.16,101.58 70.29,101.71 70.29,102.63 70.42,102.76 70.67,102.76 70.8,102.63 70.8,101.71 70.93,101.58 71.18,101.58 71.31,101.71 71.31,102.63 71.43,102.76 71.69,102.76 71.82,102.63 71.82,101.71 71.94,101.58 72.2,101.58 72.32,101.71 72.32,102.63 72.45,102.76 72.7,102.76 72.83,102.63 72.83,101.71 72.96,101.58 73.21,101.58 73.34,101.71 73.34,102.63 73.47,102.76 73.72,102.76 73.85,102.63 73.85,101.71 73.97,101.58 74.23,101.58 74.36,101.71 74.36,102.63 74.48,102.76 74.74,102.76 74.86,102.63 74.86,101.71 74.99,101.58 75.24,101.58 75.37,101.71 75.37,102.63 75.5,102.76 75.75,102.76 75.88,102.63 75.88,101.71 76.01,101.58 76.26,101.58 76.39,101.71 76.39,102.63 76.51,102.76 76.77,102.76 76.9,102.63 76.9,101.71 77.02,101.58 77.28,101.58 77.4,101.71 77.4,102.56 77.53,102.68 77.81,102.68 77.93,102.56 77.93,101.86 78.19,101.61 83.44,101.61 83.97,102.15 84.23,102.15 84.35,102.27 84.35,102.51 84.59,102.76 87.26,102.76 87.46,102.96 v2(88.02,102.96)
H_DDR1_CKE: length 92.6
  TOP w0.102: U23.K9 v4(56.95,91.4) ; U29.K9 v4(56.95,77.17)
  TOP w0.127: U27.AB18 v1(90.04,90.88)
  LY3 w0.133: v4(56.95,91.4) 57.7,91.4 58.07,91.03 58.07,90.38 57.53,89.84 57.53,88.49 57.25,88.21 57.25,87.33 58.67,85.9 58.67,85.47 57.35,84.15 57.35,82.49 56.93,82.07 56.74,82.07 56.73,82.07 56.55,82.07 56.36,81.88 56.36,81.7 56.36,81.69 56.36,81.5 56.11,81.25 56.11,80.84 56.24,80.7 56.81,80.7 56.94,80.57 56.94,80.3 56.81,80.17 56.24,80.17 56.11,80.04 56.11,79.37 56.54,78.94 56.54,78.61 56.11,78.17 56.11,77.7 56.64,77.17 v4(56.95,77.17)
  LY4 w0.133: v2(58.93,73.02) 58.48,73.47 58.48,74.49 56.95,76.02 v4(56.95,77.17) ; v4(56.95,91.4) 57.35,91.79 57.35,93.3 56.55,94.1 56.55,98.95 56.78,99.19 58.29,99.19 58.71,99.6 66.13,99.6 66.75,98.99 71.44,98.99 71.58,99.12 71.58,99.83 71.71,99.96 71.98,99.96 72.11,99.83 72.11,99.12 72.24,98.99 72.51,98.99 72.64,99.12 72.64,99.83 72.78,99.96 73.04,99.96 73.18,99.83 73.18,99.12 73.31,98.99 73.58,98.99 73.71,99.12 73.71,99.83 73.84,99.96 74.11,99.96 74.24,99.83 74.24,99.12 74.38,98.99 74.64,98.99 74.78,99.12 74.78,99.83 74.91,99.96 75.18,99.96 75.31,99.83 75.31,99.12 75.44,98.99 75.71,98.99 75.84,99.12 75.84,99.83 75.98,99.96 76.24,99.96 76.38,99.83 76.38,99.12 76.51,98.99 76.78,98.99 76.91,99.12 76.91,99.83 77.04,99.96 77.31,99.96 77.44,99.83 77.44,99.12 77.58,98.99 77.84,98.99 77.98,99.12 77.98,99.83 78.11,99.96 78.38,99.96 78.51,99.83 78.51,99.12 78.64,98.99 78.91,98.99 79.04,99.12 79.04,99.83 79.18,99.96 79.44,99.96 79.58,99.83 79.58,99.12 79.71,98.99 79.98,98.99 80.11,99.12 80.11,99.83 80.24,99.96 80.51,99.96 80.64,99.83 80.64,99.12 80.78,98.99 81.04,98.99 81.18,99.12 81.18,99.83 81.31,99.96 81.58,99.96 81.71,99.83 81.71,99.12 81.84,98.99 82.11,98.99 82.44,99.31 83.44,99.31 84.07,98.68 85.34,98.68 86.49,97.54 88.14,97.54 88.9,96.77 88.9,96.01 88.52,95.63 88.52,95 89.51,94.01 89.51,91.41 v1(90.04,90.88)
  BOTTOM w0.127: v2(58.93,73.02) R279.2
H_DDR1_CLK_N: length 106.9
  TOP w0.102: 87.71,94.14 87.71,93.43 87.76,93.37 U27.AE21
  TOP w0.103: U23.K7 v4(56.95,93) ; U29.K7 v4(56.95,78.77)
  TOP w0.112: 87.71,94.14 85.49,96.36 83.22,96.36 83.18,96.4 82.52,96.4 82.29,96.63 82.29,97.28 81.53,98.04 80.4,98.04 79.85,97.5 79.85,97.21 79.74,97.09 79.3,97.09 78.38,98.02 75.9,98.02 75.56,97.68 75.56,96.24 75.88,95.92 76.39,95.92 76.5,95.81 76.5,95.58 76.39,95.47 75.88,95.47 75.56,95.15 75.56,94.63 75.88,94.31 76.39,94.31 76.5,94.2 76.5,93.98 76.39,93.87 75.88,93.87 75.56,93.55 75.56,92.32 75.45,92.21 75.18,92.21 75.07,92.32 75.07,97.96 74.75,98.28 74.17,98.28 73.8,97.91 73.8,94.82 73.69,94.71 73.46,94.71 73.35,94.82 73.35,97.99 73.03,98.31 72.45,98.31 72.13,97.99 72.13,94.56 72.02,94.45 71.75,94.45 71.64,94.56 71.64,98 71.32,98.32 70.79,98.32 70.47,98 70.47,94.34 70.36,94.22 70.1,94.22 69.98,94.34 69.98,98 69.66,98.32 69.1,98.32 68.78,98 68.78,94.44 68.67,94.33 68.43,94.33 68.32,94.44 68.32,96.51 68,96.83 67.48,96.83 67.16,96.51 67.16,95.05 66.56,94.45 57.72,94.45 57.35,94.07 U23.K7
  LY3 w0.114: v2(60.07,73.02) 59.58,73.52 59.58,75.76 58.38,76.96 58.38,78.03 58.02,78.38 57.33,78.38 v4(56.95,78.77) 56.95,78.85 56.95,78.85 56.95,79.53 57.76,80.34 57.76,80.52 57.16,81.12 57.16,81.58 58.37,82.78 58.37,84.58 59.31,85.52 59.31,85.93 58.32,86.92 58.32,87.99 57.94,88.37 57.94,89.68 58.78,90.52 58.78,90.89 58.19,91.48 58.19,92.43 58.01,92.61 57.33,92.61 v4(56.95,93)
  BOTTOM w0.127: v2(60.07,73.02) R278.2
H_DDR1_CLK_P: length 106.5
  TOP w0.102: U27.AD21 87.76,92.05 87.44,92.38 87.44,93.22 87.38,93.29 87.38,93.95
  TOP w0.103: U23.J7 v4(57.75,93) ; U29.J7 v4(57.75,78.77)
  TOP w0.112: 87.38,93.95 87.38,93.97 85.34,96 83.07,96 83.03,96.05 82.37,96.05 81.94,96.48 81.94,97.14 81.39,97.69 80.54,97.69 80.21,97.35 80.21,97.06 79.89,96.74 79.16,96.74 78.23,97.66 76.04,97.66 75.92,97.54 75.92,96.39 76.03,96.27 76.54,96.27 76.86,95.95 76.86,95.44 76.54,95.12 76.03,95.12 75.92,95 75.92,94.78 76.03,94.67 76.54,94.67 76.86,94.35 76.86,93.83 76.54,93.51 76.03,93.51 75.92,93.4 75.92,92.17 75.6,91.85 75.03,91.85 74.71,92.17 74.71,97.81 74.6,97.92 74.32,97.92 74.16,97.77 74.16,94.67 73.84,94.35 73.31,94.35 72.99,94.67 72.99,97.84 72.88,97.95 72.6,97.95 72.48,97.84 72.48,94.41 72.16,94.09 71.61,94.09 71.29,94.41 71.29,97.85 71.18,97.96 70.94,97.96 70.83,97.85 70.83,94.19 70.51,93.87 69.95,93.87 69.63,94.19 69.63,97.85 69.52,97.96 69.25,97.96 69.14,97.85 69.14,94.29 68.82,93.97 68.29,93.97 67.97,94.29 67.97,96.36 67.85,96.47 67.63,96.47 67.52,96.36 67.52,94.9 66.71,94.09 57.87,94.09 57.7,93.92 57.7,93.61 57.91,93.4 U23.J7
  TOP w0.127: R94.2 v2(60.71,72.58)
  LY3 w0.114: v2(60.71,72.58) 60.71,73.02 59.93,73.8 59.93,75.9 58.73,77.1 58.73,78.18 58.13,78.77 v4(57.75,78.77) 57.52,78.77 57.3,78.99 57.3,79.38 58.12,80.19 58.12,80.67 57.52,81.27 57.52,81.43 58.72,82.63 58.72,84.43 59.66,85.37 59.66,86.08 58.67,87.07 58.67,88.14 58.29,88.52 58.29,89.53 59.13,90.37 59.13,91.04 58.55,91.62 58.55,92.61 58.16,93 v4(57.75,93)
H_DDR1_CSN0: length 106.5
  TOP w0.102: U29.L2 v4(56.15,83.57) ; 88.74,93.24 88.74,91.53 U27.AC19
  TOP w0.127: 88.74,93.24 88.74,94.35 87.3,95.79 87.3,97.94 87.58,98.22 v2(87.58,98.65) ; R93.2 v2(59.56,72.58) ; U23.L2 v4(56.15,97.8)
  LY3 w0.133: v4(56.15,83.57) 56.55,83.97 56.55,84.54 56.78,84.77 57.34,84.77 58.12,85.54 58.12,85.88 56.85,87.15 56.85,88.52 57.2,88.87 57.2,90.58 56.55,91.23 56.55,93.16 56.78,93.39 57.97,93.39 58.02,93.45 58.09,93.45 58.45,93.8 58.45,96.22 58.12,96.55 56.77,96.55 56.55,96.77 U23.L2 v4(56.15,97.8) 56.15,99.92 56.3,100.08 56.3,100.78 56.69,101.17 60.03,101.17 60.27,101.4 60.27,102.04 60.52,102.29 62.27,102.29 62.4,102.16 62.4,101.68 62.54,101.55 62.8,101.55 62.94,101.68 62.94,102.16 63.07,102.29 66.09,102.29 66.22,102.16 66.22,101.54 66.35,101.4 66.62,101.4 66.75,101.54 66.75,102.16 66.89,102.29 67.15,102.29 67.29,102.16 67.29,101.54 67.42,101.4 67.69,101.4 67.82,101.54 67.82,102.16 67.95,102.29 68.22,102.29 68.35,102.16 68.35,101.54 68.49,101.4 68.75,101.4 68.89,101.54 68.89,102.16 69.02,102.29 69.29,102.29 69.42,102.16 69.42,101.54 69.55,101.4 69.82,101.4 69.95,101.54 69.95,102.16 70.09,102.29 70.35,102.29 70.49,102.16 70.49,101.54 70.62,101.4 70.89,101.4 71.02,101.54 71.02,102.16 71.15,102.29 71.42,102.29 71.55,102.16 71.55,101.54 71.69,101.4 71.95,101.4 72.09,101.54 72.09,102.16 72.22,102.29 72.9,102.29 73.04,102.43 73.04,102.94 73.17,103.08 73.44,103.08 73.57,102.94 73.57,102.43 73.7,102.29 73.97,102.29 74.1,102.43 74.1,102.94 74.24,103.08 74.5,103.08 74.64,102.94 74.64,102.43 74.77,102.29 75.04,102.29 75.17,102.43 75.17,102.94 75.3,103.08 75.57,103.08 75.7,102.94 75.7,102.43 75.84,102.29 76.1,102.29 76.24,102.43 76.24,102.94 76.37,103.08 76.64,103.08 76.77,102.94 76.77,102.43 76.9,102.29 77.19,102.29 77.32,102.16 77.32,101.49 77.46,101.36 77.72,101.36 77.86,101.49 77.86,102.16 77.99,102.29 78.26,102.29 78.39,102.16 78.39,101.49 78.52,101.36 78.79,101.36 78.92,101.49 78.92,102.16 79.06,102.29 79.32,102.29 79.46,102.16 79.46,101.49 79.59,101.36 79.86,101.36 79.99,101.49 79.99,102.16 80.12,102.29 80.39,102.29 80.52,102.16 80.52,101.49 80.66,101.36 80.92,101.36 81.06,101.49 81.06,102.16 81.19,102.29 82.26,102.29 83.97,100.59 86.26,100.59 86.72,100.13 86.72,99.19 86.84,99.06 87.17,99.06 87.3,99.19 87.3,99.87 87.43,100 88.02,100 88.16,99.87 88.16,98.79 88.02,98.65 v2(87.58,98.65)
  BOTTOM w0.127: v4(56.15,83.57) 56.15,83.33 55.75,82.93 55.75,81.61 54.15,80.01 54.15,76.81 54.71,76.25 55.03,76.25 57.81,73.46 59.25,73.46 59.56,73.15 v2(59.56,72.58)
H_DDR1_D0: length 33.2
  TOP w0.102: U23.H7 v4(59.35,93)
  TOP w0.127: U27.AA23 v1(86.14,90.23)
  LY3 w0.133: v1(86.14,90.23) 83.57,90.23 83.44,90.37 83.44,90.67 83.3,90.8 83.04,90.8 82.9,90.67 82.9,90.37 82.77,90.23 82.5,90.23 82.37,90.37 82.37,90.67 82.24,90.8 81.97,90.8 81.84,90.67 81.84,90.37 81.7,90.23 81.47,90.23 80.92,90.78 76.43,90.78 75.41,91.8 73.81,91.8 72.9,92.71 72.29,92.71 71.35,91.77 70.97,91.77 70.08,92.66 69.55,92.66 68.66,91.77 68.43,91.77 67.59,92.6 67.19,92.6 66.38,91.8 59.93,91.8 59.75,91.99 59.75,92.6 v4(59.35,93)
H_DDR1_D1: length 34
  TOP w0.102: 85.62,91.21 85.49,91.34 85.49,91.34 85.3,91.53 84.93,91.53 84.86,91.46 ; U23.F8 v4(60.95,92.2)
  TOP w0.103: 85.62,91.21 U27.AC24
  TOP w0.127: 84.86,91.46 79.15,91.46 78.98,91.63 78.24,91.63 v2(77.88,91.26)
  LY3 w0.133: v4(60.95,92.2) 61.34,92.59 65.46,92.59 65.96,93.09 73.2,93.09 74.09,92.21 76.74,92.21 76.87,92.34 76.87,92.53 76.74,92.66 74.4,92.66 74.27,92.79 74.27,92.98 74.4,93.11 77.57,93.11 77.88,92.81 v2(77.88,91.26)
H_DDR1_D2: length 30.8
  TOP w0.102: U23.F7 v4(60.95,93) ; 84.4,90.88 85.49,90.88 U27.AB24
  TOP w0.127: 84.4,90.88 79.37,90.88 79.27,90.78 77.62,90.78 77.19,91.21 v2(76.66,91.21)
  LY4 w0.133: v2(76.66,91.21) 72.44,95.43 71.42,95.43 71.03,95.03 71.03,94.77 70.9,94.64 70.63,94.64 70.5,94.77 70.5,95.3 70.37,95.43 70.1,95.43 69.97,95.3 69.97,95.1 69.84,94.97 69.57,94.97 69.44,95.1 69.44,95.3 69.31,95.43 62.46,95.43 60.95,93.92 v4(60.95,93)
H_DDR1_D3: length 34.3
  TOP w0.102: 85.19,93.24 85.49,92.95 85.49,92.35 85.81,92.02 U27.AD24 ; U23.H8 v4(59.35,92.2)
  TOP w0.127: v2(78.18,94.41) 78.18,93.68 79.61,92.25 82.95,92.25 84.07,93.37 85.06,93.37 85.19,93.24
  LY3 w0.133: v4(59.35,92.2) 58.93,92.62 58.93,93.04 58.86,93.11 58.86,95.14 59.07,95.35 59.77,95.35 61.1,94.02 77.79,94.02 v2(78.18,94.41)
H_DDR1_D4: length 33.1
  TOP w0.102: U23.E3 v4(61.75,97)
  TOP w0.127: U27.AB23 v1(86.14,90.88)
  LY3 w0.133: v1(86.14,90.88) 86.14,96.08 85.78,96.44 85.78,96.93 85.42,97.28 82.05,97.28 81.15,98.17 79.88,98.17 78.05,96.34 76.45,96.34 75.4,97.39 62.14,97.39 v4(61.75,97)
H_DDR1_D5: length 34.6
  TOP w0.102: U23.H3 v4(59.35,97) ; 84.56,92.18 84.37,91.99 84.17,91.99
  TOP w0.103: 84.56,92.18 85.31,92.18 85.49,92.01 85.49,91.72 85.68,91.53 86.14,91.53 U27.AC23
  TOP w0.127: 84.17,91.99 84.16,91.99 79.45,91.99 79.31,92.14 78.48,92.14 77.27,93.34 v2(77.27,95.68)
  LY3 w0.133: v2(77.27,95.68) 74.8,95.68 74.7,95.78 74.7,96.08 74.84,96.22 75.31,96.22 75.51,96.43 75.51,96.62 75.31,96.82 67.01,96.82 66.62,96.44 61.65,96.44 61.35,96.74 61.35,97.2 61.15,97.39 59.74,97.39 v4(59.35,97)
H_DDR1_D6: length 34.5
  TOP w0.102: U27.AD23 86.14,92.19 86.14,93.24 ; U23.F2 v4(60.95,97.8)
  TOP w0.127: 86.14,93.24 86.14,93.33 85.51,93.96 83.97,93.96 82.17,95.76 79.37,95.76 77.9,97.23 v2(76.33,97.23)
  LY3 w0.133: v2(76.33,97.23) 76.33,97.79 76.76,98.22 78.1,98.22 78.23,98.35 78.23,98.69 78.1,98.83 67.64,98.83 67.46,98.65 67.46,98.45 67.21,98.2 61.35,98.2 v4(60.95,97.8)
H_DDR1_D7: length 34.3
  TOP w0.102: U23.G2 v4(60.15,97.8)
  TOP w0.127: v2(77.56,96.79) 78.96,95.38 82.06,95.38 83.82,93.62 85.45,93.62 85.81,93.26 U27.AE24
  LY3 w0.133: v4(60.15,97.8) 60.55,98.19 60.55,98.85 60.84,99.14 78.93,99.14 79.12,98.95 79.12,98.3 78.61,97.79 77.85,97.79 77.56,97.5 v2(77.56,96.79)
H_DDR1_D8: length 31.2
  TOP w0.102: U23.A2 v4(64.95,97.8) ; U27.AA24 85.49,90.24 84.4,90.24
  TOP w0.127: v2(80.75,90.12) 81.14,90.12 81.25,90.24 84.4,90.24
  LY4 w0.133: v4(64.95,97.8) 75.28,97.8 75.41,97.66 75.41,97.11 75.54,96.98 75.74,96.98 75.87,97.11 75.87,97.66 76,97.8 76.75,97.8 77.04,97.51 77.04,96.55 77.34,96.24 77.77,96.24 77.95,96.06 77.95,95.45 77.67,95.17 77.67,94.31 78.05,93.93 78.46,93.93 78.59,93.8 78.59,93.4 78.77,93.22 79.24,93.22 79.38,93.08 79.38,92.71 79.76,92.33 80.7,92.33 80.9,92.13 80.9,91.92 80.74,91.77 80.12,91.77 79.98,91.63 79.98,91.37 80.12,91.24 80.61,91.24 80.75,91.1 v2(80.75,90.12)
H_DDR1_D9: length 33.4
  TOP w0.102: U23.B8 v4(64.15,92.2)
  TOP w0.127: v2(70.46,91.31) 70.97,91.31 71.4,91.74 71.4,92.84 71.55,92.99 71.81,92.99 71.93,92.86 71.93,90.75 72.06,90.63 72.31,90.63 72.48,90.79 72.48,93.18 72.81,93.51 73.45,93.51 73.75,93.2 73.75,90.84 74.03,90.56 74.28,90.56 74.55,90.3 74.55,89.92 74.87,89.6 77.03,89.6 77.53,89.09 77.53,88.51 78.23,87.81 79.96,87.81 80.76,88.61 U27.W25
  LY4 w0.133: v2(70.46,91.31) 69.98,91.8 69.72,91.8 69.56,91.95 69.56,92.17 69.4,92.33 69.18,92.33 69.03,92.17 69.03,91.95 68.87,91.8 64.55,91.8 v4(64.15,92.2)
H_DDR1_D10: length 39
  TOP w0.102: U27.Y23 86.14,88.93 85.49,88.93 ; U23.A7 v4(64.95,93)
  TOP w0.103: 85.49,88.93 84.4,88.93
  TOP w0.127: v4(64.95,93) 65.03,92.91 65.79,92.91 66.27,93.4 67.19,93.4 67.32,93.27 67.32,92.07 67.44,91.95 67.64,91.95 67.77,92.07 67.77,93.34 67.95,93.52 68.2,93.52 68.33,93.4 68.33,92.07 68.46,91.95 68.71,91.95 68.84,92.07 68.84,93.37 68.97,93.5 69.22,93.5 69.35,93.37 69.35,92.02 69.47,91.9 69.65,91.9 69.78,92.02 69.78,93.3 69.98,93.5 70.24,93.5 70.36,93.37 70.36,92 70.49,91.87 70.74,91.87 70.87,92 70.87,93.27 71,93.4 71.94,93.4 72.52,93.97 73.92,93.97 74.19,93.7 74.19,91.16 74.68,90.68 77.09,90.68 77.47,90.3 77.47,89.79 77.72,89.53 78.1,89.53 78.36,89.28 78.36,88.39 78.61,88.14 79.78,88.14 80.53,88.89 82.02,88.89 82.06,88.93 84.4,88.93
H_DDR1_D11: length 31.9
  TOP w0.102: U23.C8 v4(63.35,92.2)
  TOP w0.127: v2(75.29,91.21) 75.82,91.21 76.49,91.88 79.12,91.88 79.27,91.74 84.63,91.74 84.75,91.86 U27.AD25
  LY4 w0.133: v2(75.29,91.21) 73.94,91.21 73.81,91.34 73.81,93.22 73.53,93.5 73.17,93.5 72.62,92.95 72.43,92.95 72.24,93.13 72.24,93.32 72.79,93.87 72.79,94.06 72.54,94.31 66.98,94.31 66.24,95.05 62.64,95.05 62.15,94.56 62.15,92.77 62.32,92.59 62.95,92.59 v4(63.35,92.2)
H_DDR1_D12: length 31.2
  TOP w0.102: U23.C3 v4(63.35,97)
  TOP w0.127: v2(78.79,91.21) U27.AC25
  LY4 w0.133: v4(63.35,97) 63.35,96.45 63.48,96.32 70.54,96.32 71.3,97.08 73.99,97.08 74.75,96.32 75.69,96.32 75.97,96.04 75.97,94.23 76.07,94.13 76.38,94.13 76.45,94.21 76.45,94.89 76.57,95.01 76.82,95.01 76.95,94.88 76.95,93.13 77.4,92.68 77.4,92.08 77.53,91.95 77.75,91.95 77.88,92.08 77.88,92.56 78.04,92.72 78.23,92.72 78.87,92.07 79.07,92.07 79.21,91.94 79.21,91.62 v2(78.79,91.21)
